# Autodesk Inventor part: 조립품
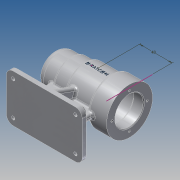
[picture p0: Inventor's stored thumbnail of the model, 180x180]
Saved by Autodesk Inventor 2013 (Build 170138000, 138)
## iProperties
Created: 2016-06
Part Number: 조립품
Material: 알루미늄 6061
Document SubType Name: Modeling
Designer: Administrator
Density: 2.71 g/cm^3
Mass: 669.883 g
Surface Area: 649.572 cm^2
Volume: 247.189 cm^3
Author: Administrator
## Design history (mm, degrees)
sketch "스케치1"
  geometry: L1 (56, 34)-(56, 0); L2 (56, 0)-(-56, 0); L3 (-56, 0)-(-56, 25); L4 (56, 34)-(28, 34); L5 (28, 34)-(28, 30); L6 (28, 30)-(-11, 30); L7 (-11, 30)-(-11, 27); L8 (-11, 27)-(-31, 27); L9 (-31, 27)-(-31, 25); L10 (-31, 25)-(-56, 25); 2 further points
  constraints: 20 end point, 5 parallel, 3 perpendicular, 1 coincident, 1 midpoint
  dimensions: "d0" = 112 distance between parallel lines of L1 L3; "d2" = 68 diameter of L4 L2; "d3" = 60 diameter of L6 L2; "d4" = 54 diameter of L8 L2; "d5" = 50 diameter of L10 L2; "d6" = 25 distance between parallel lines of L3 L9; "d7" = 45 distance between parallel lines of L7 L3; "d8" = 84 distance between parallel lines of L3 L5
sketch "스케치2"
  geometry: 1 further point
sketch "스케치3"
  geometry: 1 further point
revolve "회전1" stored, may be unused: angle "d9" = 90 deg
sketch "스케치4"
  geometry: L1 (-31, -25)-(-56, -25) reference; L2 (-56, -25)-(-56, 25) reference; L3 (-56, 25)-(-31, 25) reference; L4 (-31, 25)-(-31, 27) reference; L5 (-31, 27)-(-11, 27) reference; L6 (-11, 27)-(-11, 30) reference; L7 (-11, 30)-(28, 30) reference; L8 (28, 30)-(28, 34) reference; L9 (28, 34)-(56, 34) reference; L10 (56, 34)-(56, -34) reference; L11 (56, -34)-(28, -34) reference; L12 (28, -34)-(28, -30) reference; L13 (28, -30)-(-11, -30) reference; L14 (-11, -30)-(-11, -27) reference; L15 (-11, -27)-(-31, -27) reference; L16 (-31, -27)-(-31, -25) reference; L17 (-36, 0)-(-36, -60); L18 (-36, 0)-(36, 0); L19 (28, -34)-(28, 34) reference; L20 (36, 0)-(36, -60); L21 (-56, -60)-(56, -60); L22 (56, -60)-(56, -70); L23 (56, -70)-(-56, -70); L24 (-56, -70)-(-56, -60); 2 further points
  constraints: 14 end point, 4 parallel, 2 perpendicular, 2 point on line, 1 coincident, 1 horizontal, 1 midpoint, 1 vertical alignment
  dimensions: "d10" = 70 distance from line of point (0, 0) L23; "d11" = 10 distance between parallel lines of L23 L21; "d12" = 112 distance between parallel lines of L22 L24; "d13" = 20 distance of L17.end L21.start; "d14" = 20 distance of L21.end L20.end (derived)
  node "절단 모서리 투영1"
extrude "돌출1" join sketch "스케치4" stored distance "d15" = 8; taper "d16" = 0 deg
extrude "돌출2" join sketch "스케치4" stored distance "d17" = 70; taper "d18" = 0 deg
sketch "스케치5"
  geometry: L1 (-60, -4)-(-60, -35) reference; L2 (-60, -35)-(-70, -35) reference; L3 (-70, -35)-(-70, 35) reference; L4 (-70, 35)-(-60, 35) reference; L5 (-60, 35)-(-60, 4) reference; L6 (-60, 4)-(-29.732, 4) reference; L7 (-29.732, -4)-(-60, -4) reference; L8 (0, 6.162)-(-60, 28); L9 (-60, -35)-(-60, 35) reference; L10 (0, -6.162)-(-60, -28); L11 (0, 6.162)-(0, -6.162); A1 r 30 centre (0, 0) between (-29.732, -4) and (-29.732, 4) reference; 2 further points
  constraints: 6 end point, 2 point on line, 1 coincident, 1 midpoint, 1 parallel
  dimensions: "d19" = 110 deg angle of L8 L5; "d20" = 110 deg angle of L10 L1; "d21" = 7 distance of L8.end L4.end; "d22" = 7 distance of L1.end L10.end (derived)
extrude "돌출3" join sketch "스케치5" stored distance "d23" = 8; taper "d24" = 0 deg
sketch "스케치6"
  geometry: L1 (-56, 25)-(-31, 25) reference; L2 (-31, 25)-(-31, 27) reference; L3 (-31, 27)-(-11, 27) reference; L4 (-11, 27)-(-11, 30) reference; L5 (-11, 30)-(28, 30) reference; L6 (28, 30)-(28, 34) reference; L7 (28, 34)-(56, 34) reference; L8 (56, 34)-(56, -34) reference; L9 (56, -34)-(36, -34) reference; L10 (36, -34)-(36, -60) reference; L11 (36, -60)-(56, -60) reference; L12 (56, -60)-(56, -70) reference; L13 (56, -70)-(-56, -70) reference; L14 (-56, -70)-(-56, -60) reference; L15 (-56, -60)-(-36, -60) reference; L16 (-36, -60)-(-36, -25) reference; L17 (-36, -25)-(-56, -25) reference; L18 (-56, -25)-(-56, 25) reference; L19 (56, -34)-(56, 34) reference; L20 (-50, 0)-(-50, 10.5); L21 (-50, 10.5)-(-47, 10.5); L22 (-47, 10.5)-(-47, 16); L23 (-47, 16)-(-43, 16); L24 (-43, 16)-(-43, 17.5); L25 (-43, 17.5)-(-25, 17.5); L26 (-25, 17.5)-(-25, 21); L27 (-25, 21)-(-13, 21); L28 (-13, 21)-(-13, 24); L29 (-13, 24)-(41, 24); L30 (41, 24)-(41, 21); L31 (41, 21)-(56, 21); L32 (-50, 0)-(56, 0); L33 (56, 21)-(56, 0); 2 further points
  constraints: 28 end point, 8 parallel, 5 perpendicular, 2 midpoint, 1 collinear, 1 horizontal alignment, 1 point on line
  dimensions: "d30" = 3 distance between parallel lines of L22 L20; "d32" = 4 distance between parallel lines of L24 L22; "d33" = 18 distance between parallel lines of L26 L24; "d34" = 12 distance between parallel lines of L28 L26; "d35" = 54 distance between parallel lines of L30 L28; "d36" = 15 distance between parallel lines of L8 L30; "d37" = 21 diameter of L21 L32; "d38" = 32 diameter of L23 L32; "d39" = 35 diameter of L25 L32; "d40" = 42 diameter of L27 L32; "d41" = 48 diameter of L29 L32; "d42" = 42 diameter of L31 L32
revolve "회전2" sketch "스케치6" stored, may be unused: angle "d43" = 90 deg
fillet "모깎기1" dims "d44" = 10
chamfer "모따기1" distance "d45" = 4; stored, may be unused: second distance "d46" = 2, angle "d47" = 45 deg
chamfer "모따기2" distance "d48" = 1; stored, may be unused: second distance "d49" = 2, angle "d50" = 45 deg
fillet "모깎기2" dims "d51" = 3
fillet "모깎기3" dims "d52" = 0.3
fillet "모깎기4" dims "d53" = 3
sketch "스케치7"
  geometry: A1 r 6 centre (92, 6) between (92, 0) and (98, 6) reference; A2 r 6 centre (92, 56) between (98, 56) and (92, 62) reference; A3 r 6 centre (0, 56) between (0, 62) and (-6, 56) reference; A4 r 6 centre (0, 6) between (-6, 6) and (0, 0) reference; 5 further points
  constraints: 4 coincident
  dimensions: "d54" = 92 distance of point (92, 6) point (0, 6) (derived); "d55" = 50 distance of point (92, 56) A1.centre (derived)
hole "구멍1" sketch "스케치7" at (92, 6), (92, 56), (0, 6), (0, 56) diameter "d56" = 5; stored, may be unused: countersink angle "d60" = 90 deg, drill point angle "d62" = 118 deg; dims "d57" = 6, "d58" = 9, "d59" = 4, "d61" = 11.5
fillet "모깎기5" dims "d63" = 3
fillet "모깎기8" dims "d66" = 3
fillet "모깎기9" dims "d67" = 10
fillet "모깎기10" dims "d68" = 3
fillet "모깎기11" dims "d69" = 3
sketch "스케치8"
  geometry: C1 r 34 at (0, 0) reference; 1 further point
  constraints: 1 vertical alignment
  dimensions: "d70" = 26 distance of point (0, 26) C1.centre
hole "구멍2" sketch "스케치8" at (0, 26) diameter "d71" = 3.242; stored, may be unused: countersink angle "d75" = 90 deg, drill point angle "d77" = 118 deg; dims "d72" = 8, "d73" = 9, "d74" = 4, "d76" = 11
node "작업 평면1"
sketch "스케치9"
  geometry: L1 (56, -34)-(56, 34) reference; 2 further points
  constraints: 1 horizontal alignment, 1 other
  dimensions: "d82" = 48 distance from line of L1 point (8, 0)
node "솔리드1"
pattern_circular "원형 패턴1" dims angle "d79" = 360 deg
node "절단 모서리 투영2"
node "절단 모서리 투영3"
